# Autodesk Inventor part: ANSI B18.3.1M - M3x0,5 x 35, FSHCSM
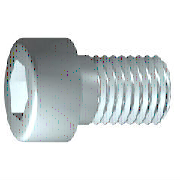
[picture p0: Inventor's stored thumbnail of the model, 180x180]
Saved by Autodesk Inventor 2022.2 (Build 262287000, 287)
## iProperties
Created: 2021-02
Part Number: ANSI B18.3.1M - M3x0,5 x 35, FSHCSM
Material: Acciaio, Dolce
Description: Vite forgiata a testa incassata - Metrico
Document SubType Name: Modeling
Standard: ANSI B18.3.1M
Designer: 18907419
Standard Revision: 1979
Standards Organization: ANSI
Language: it-IT
Size Designation: M3x0,5 x 35
Categories: <MemberInstance><Categories><Category DisplayName="Elementi di fissaggio" InternalName="e4da775c-781d-43d5-af7c-5136215cf5a6" Mnemonic="FSTN"><Category DisplayN
Density: 7.85 g/cm^3
Appearance: Semilucidato
IsCustomPart: 0
Author: 18907419
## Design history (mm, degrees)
sketch "Schizzo1"
  geometry: L1 (-0.667, 0)-(35, 0); L2 (35, 0)-(35, 1.5); L3 (35, 1.5)-(17, 1.5); L4 (17, 1.5)-(16.693, 1.5); L5 (16.693, 1.5)-(0, 1.5); L6 (0, 1.5)-(0, 2.75); L7 (0, 2.75)-(-3, 2.75); L8 (-3, 2.75)-(-3, 1.443); L9 (-3, 1.443)-(-1.5, 1.443); L10 (-1.5, 1.443)-(-0.667, 0); L11 (-10.6, 0)-(42.6, 0) reference; L12 (0, -0.55)-(0, 3.3) reference; L13 (17, 1.5)-(0, 1.5)
  constraints: 22 end point, 6 parallel, 2 collinear, 2 perpendicular, 1 horizontal, 1 point on line
  dimensions: "d1" = 18 distance from line of L3.end L2 (= GEL); "d2" = 0.30683 distance of L4.end L3.end (computed from GAL); "d3" = 3 distance between parallel lines of L8 L6 (= KOH); "d4" = 1.5 distance of L8.end L9.end (= INTI); "d5" = 60 deg angle of L10 L1; "d6" = 3 diameter of L3 L1 (= GD); "d7" = 3 diameter of L5 L1 (= BDM); "d8" = 2.88675 diameter of L9 L1 (= 1.1547 x SW); "d9" = 5.5 diameter of L7 L1 (= KOD); "d26" = 35 distance between parallel lines of L12 L2 (= NLG)
revolve "Corpo" sketch "Schizzo1" stored, may be unused: angle "d10" = 90 deg
sketch "Schizzo2"
  geometry: L1 (0, -3.85)-(0, 3.85) reference; L2 (-3.85, 0)-(3.85, 0) reference; L3 (1.443, 0)-(0.722, -1.25); L4 (0.722, -1.25)-(-0.722, -1.25); L5 (-0.722, -1.25)-(-1.443, 0); L6 (-1.443, 0)-(-0.722, 1.25); L7 (-0.722, 1.25)-(0.722, 1.25); L8 (0.722, 1.25)-(1.443, 0); 2 further points
  constraints: 12 end point, 1 coincident, 1 horizontal alignment, 1 point on line, 12 other
extrude "Intaglio" join sketch "Schizzo2" stored distance "d11" = 10; taper "d12" = 0 deg
workplane "Work Plane1"
fillet "Fillet2" dims "d30" = 0.1 (= R)
body "Solid1"
fillet "Raccordo1" dims "d17" = 0.3 (= RR)
feature "Filettatura" dims "d13" = 18 (= GEL), "d14" = 0
chamfer "Smusso1" distance "d15" = 0.30673 (= -0.5 x SPD + 0.5 x GD); stored, may be unused: second distance "d16" = 0.30673 (= GUL), angle "d27" = 45 deg
other parameters: "GD" = 3 (= NND) [user parameter; used in 2 equation terms], "NLG" = 35 [user parameter; used in 1 equation term], "GEL" = 18 [user parameter; used in 2 equation terms], "KOD" = 5.5 [user parameter; used in 1 equation term], "KOH" = 3 [user parameter; used in 1 equation term], "INTI" = 1.5 [user parameter; used in 1 equation term], "GAL" = 0.30673 (= 0.61345 x PTC) [user parameter; used in 1 equation term], "GUL" = 0.30673 (= 0.61345 x PTC) [user parameter; used in 1 equation term], "BDM" = 3 (= NND) [user parameter; used in 1 equation term], "SW" = 2.5 [user parameter; used in 2 equation terms], "RR" = 0.3 [user parameter; used in 1 equation term], "SPD" = 2.38655 [user parameter; used in 1 equation term], "d19" = 0, "d28" = 0, "d29" = 0, "R" = 0.1 [user parameter; used in 1 equation term], "TOA" = 30 deg [user parameter], "THREADDIA" = 3 [user parameter; used in 1 equation term], "PTC" = 0.5 [user parameter; used in 4 equation terms], "NND" = 3 [user parameter; used in 2 equation terms], "E0" = 2.8875 (= 1.155 x SW) [user parameter], "GD1" = 2.38655 (= THREADDIA - 1.2269 x PTC) [user parameter]
